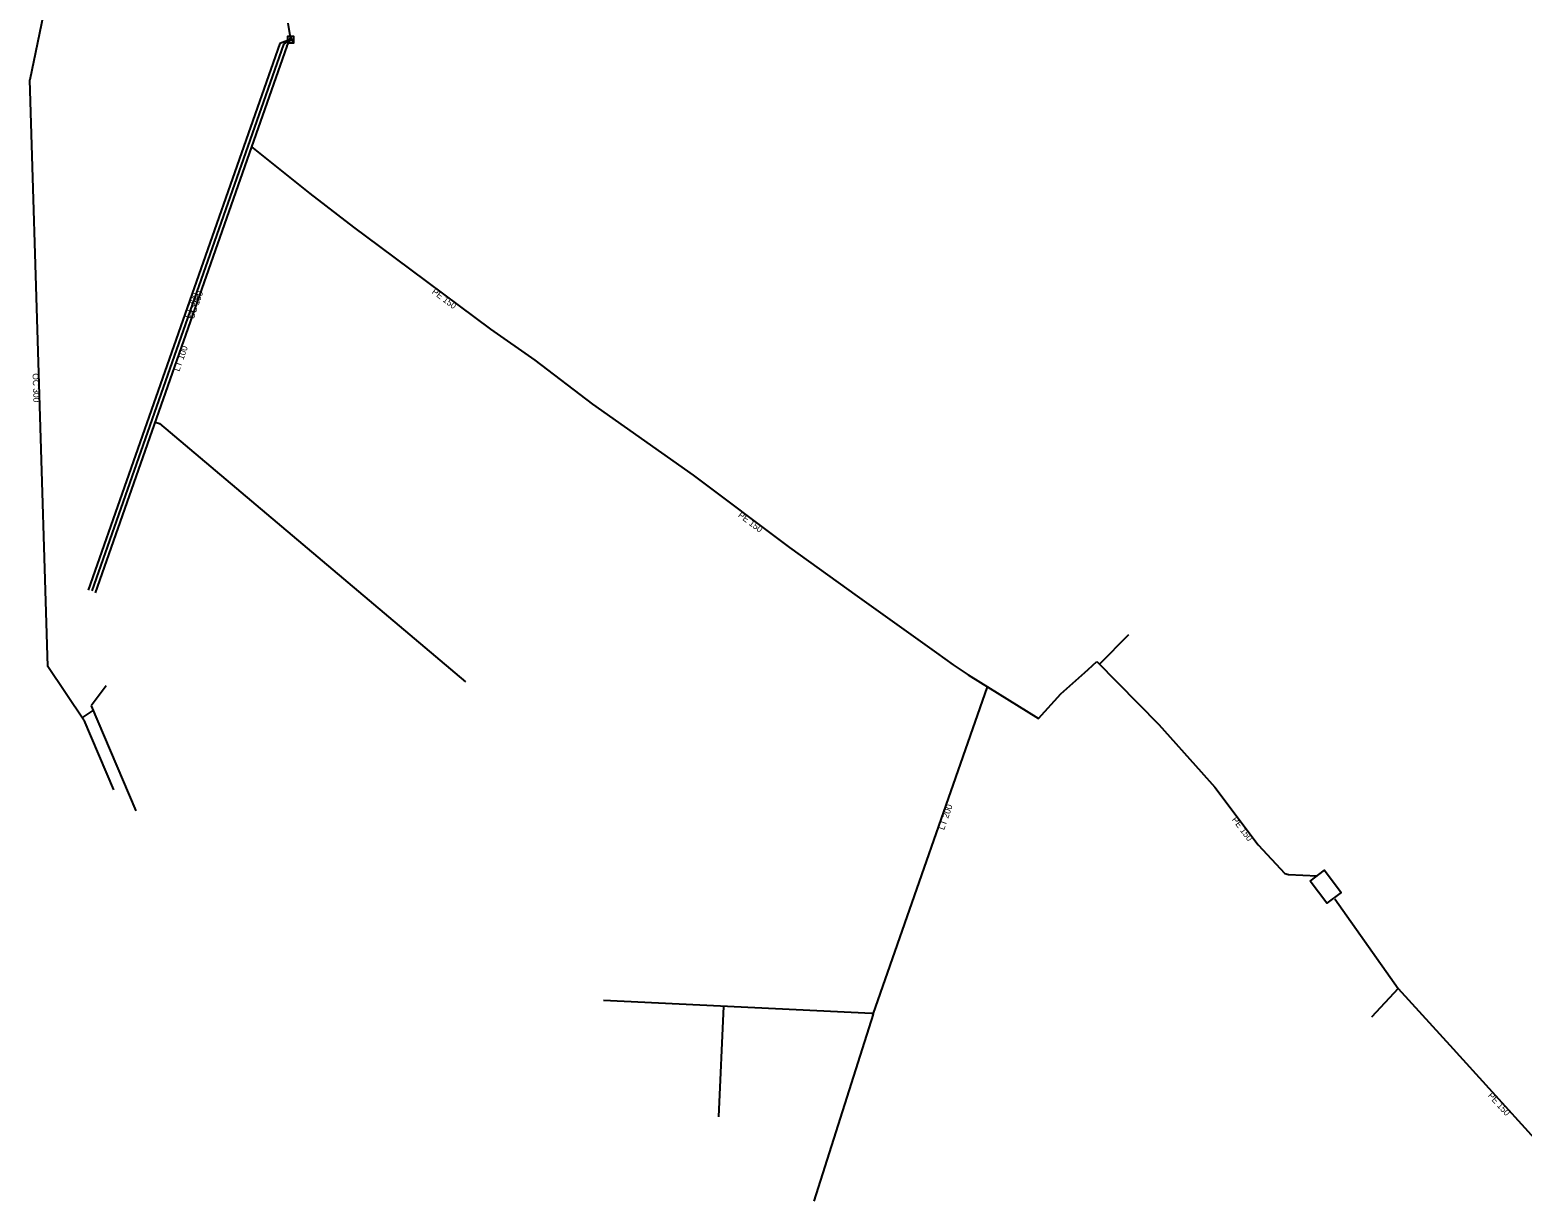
# Model space of a CAD drawing. Extents: x -513141 to -512601, y -1130827 to -1130115.
# Drawn here: x -513063.1 to -512832.4, y -1130617.5 to -1130436.4 of the extents above; entities that cross this region are included whole.
import ezdxf

# ---------------------------------------------------------------- set-up
doc = ezdxf.new("R2010")
doc.units = 0
for name, color, linetype in [('Default', 7, 'Continuous'), ('MoLevel 10', 7, 'Continuous'), ('MoLevel 13', 7, 'Continuous'), ('MoLevel 15', 7, 'Continuous'), ('MoLevel 17', 7, 'Continuous'), ('MoLevel 32', 7, 'Continuous')]:
    doc.layers.add(name, color=color, linetype=linetype)

# ---------------------------------------------------------------- blocks, each defined once
blk = doc.blocks.new('0.13')
at = {"layer": 'Default'}
for p, q in [((0, 0.04), (-0.035, -0.035)), ((0, 0.04), (0.035, -0.035)), ((-0.0235, -0.0095), (0.0235, -0.0095))]:
    blk.add_line(p, q, dxfattribs=at)
blk.add_lwpolyline([(-0.05, -0.05), (0.05, -0.05), (0.05, 0.05), (-0.05, 0.05), (-0.05, -0.05)], dxfattribs=at)

msp = doc.modelspace()

# ---------------------------------------------------------------- linework, layer by layer
at = {"layer": 'MoLevel 10'}
for p, q in [((-513057.15, -1130415.35), (-513063.11, -1130444.16)), ((-513023.23, -1130435.43), (-513022.8, -1130437.96)), ((-513024.48, -1130438.55), (-513054.08, -1130523.03)), ((-513023.91, -1130438.69), (-513053.51, -1130523.17)), ((-513023.4, -1130438.97), (-513028.85, -1130454.54)), ((-513022.8, -1130437.96), (-513024.48, -1130438.55)), ((-513023.91, -1130438.69), (-513022.8, -1130437.96)), ((-513023.4, -1130438.97), (-513022.8, -1130437.96)), ((-513060.32, -1130534.87), (-513063.11, -1130444.16)), ((-513028.85, -1130454.54), (-513053, -1130523.45)), ((-513028.85, -1130454.54), (-513019.82, -1130461.73)), ((-513019.82, -1130461.73), (-513013.09, -1130466.95)), ((-513013.09, -1130466.95), (-513009.06, -1130469.93)), ((-513009.06, -1130469.93), (-512991.89, -1130482.7)), ((-512991.89, -1130482.7), (-512985.06, -1130487.49)), ((-512985.06, -1130487.49), (-512976.15, -1130494.32)), ((-512976.15, -1130494.32), (-512960.59, -1130505.26)), ((-512960.59, -1130505.26), (-512945.7, -1130516.44)), ((-512945.7, -1130516.44), (-512935.25, -1130523.96)), ((-512935.25, -1130523.96), (-512922.95, -1130532.73)), ((-512922.95, -1130532.73), (-512920.39, -1130534.61)), ((-513054.78, -1130543.17), (-513060.32, -1130534.87)), ((-512920.39, -1130534.61), (-512918.08, -1130536.12)), ((-512903.74, -1130539.08), (-512900.05, -1130535.77)), ((-512900.05, -1130535.77), (-512899.52, -1130535.31)), ((-512899.52, -1130535.31), (-512898.17, -1130534.09)), ((-512898.17, -1130534.09), (-512888.62, -1130543.83)), ((-513051.29, -1130537.82), (-513053.62, -1130540.93)), ((-512932.78, -1130588.58), (-512915.07, -1130538)), ((-512918.08, -1130536.12), (-512907.23, -1130542.9)), ((-512907.23, -1130542.9), (-512903.74, -1130539.08)), ((-513055.04, -1130542.79), (-513053.32, -1130541.64)), ((-513053.62, -1130540.93), (-513046.71, -1130557.16)), ((-513054.78, -1130543.17), (-513050.18, -1130553.9)), ((-512888.62, -1130543.83), (-512882.05, -1130551.12)), ((-512882.05, -1130551.12), (-512879.95, -1130553.5)), ((-512879.95, -1130553.5), (-512873.23, -1130562.39)), ((-512873.23, -1130562.39), (-512869.15, -1130566.83)), ((-512869.15, -1130566.83), (-512868.59, -1130567)), ((-512868.59, -1130567), (-512864.12, -1130567.19)), ((-512861.39, -1130570.76), (-512851.63, -1130584.6)), ((-512851.63, -1130584.6), (-512847.92, -1130588.71)), ((-512932.78, -1130588.58), (-512941.92, -1130617.49)), ((-512847.92, -1130588.71), (-512843.65, -1130593.36)), ((-512843.65, -1130593.36), (-512830.55, -1130607.78))]:
    msp.add_line(p, q, dxfattribs=at)
at = {"layer": 'MoLevel 15'}
for p, q in [((-513043.76, -1130497.07), (-513043.07, -1130497.31)), ((-513043.07, -1130497.31), (-512995.79, -1130537.2)), ((-512897.73, -1130534.45), (-512893.26, -1130529.91)), ((-512932.99, -1130588.47), (-512974.44, -1130586.48)), ((-512851.63, -1130584.6), (-512855.72, -1130589.06)), ((-512955.87, -1130587.37), (-512956.69, -1130604.46)), ((-512932.78, -1130588.58), (-512932.99, -1130588.47))]:
    msp.add_line(p, q, dxfattribs=at)
at = {"layer": 'MoLevel 17'}
msp.add_lwpolyline([(-512865.22, -1130568.05), (-512863.02, -1130566.32), (-512860.43, -1130569.78), (-512862.64, -1130571.41)], close=True, dxfattribs=at)

# ---------------------------------------------------------------- block references
at = {"layer": 'MoLevel 13', "xscale": 10, "yscale": 10}
msp.add_blockref('0.13', (-513022.8, -1130437.96), dxfattribs=at)

# ---------------------------------------------------------------- texts
at = {"layer": 'MoLevel 32'}
for s, rotation, p in [('LT 300', 70.6906, (-513038.36, -1130481.11)), ('OC 150', 70.6906, (-513037.79, -1130481.25)), ('PE 150', 323.3604, (-513001.06, -1130477.1)), ('LT 100', 70.6909, (-513040.01, -1130489.31)), ('OC 300', 271.7617, (-513062.69, -1130489.54)), ('PE 150', 323.0993, (-512953.73, -1130511.63)), ('LT 200', 70.7015, (-512921.8, -1130560.19)), ('PE 150', 307.0858, (-512877.37, -1130558.53)), ('PE 150', 312.2539, (-512837.82, -1130601.23))]:
    msp.add_text(s, height=0.975, rotation=rotation, dxfattribs=at).set_placement(p)

doc.saveas('drawing.dxf')
